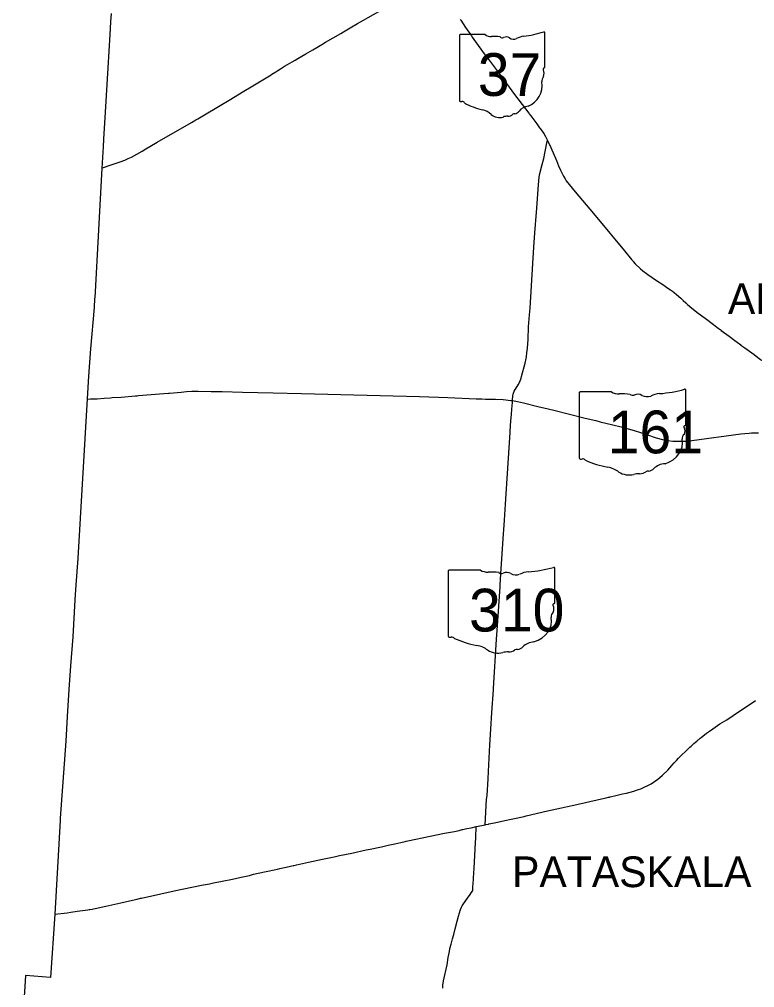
# Model space of a CAD drawing. Extents: x 1761803 to 2441803, y 509895 to 949895.
# Drawn here: x 1889790 to 1937717, y 814167 to 877258 of the extents above; entities that cross this region are included whole.
import ezdxf

# ---------------------------------------------------------------- set-up
doc = ezdxf.new("R2010")
doc.units = 0
for name, color, linetype in [('GM_X_County', 7, 'Continuous'), ('GM_X_County_Road', 7, 'Continuous'), ('GM_X_Minor_Lake', 7, 'Continuous'), ('GM_X_Minor_River_Text', 7, 'Continuous'), ('GM_X_Township_Road', 7, 'Continuous')]:
    doc.layers.add(name, color=color, linetype=linetype)

msp = doc.modelspace()

# ---------------------------------------------------------------- linework, layer by layer
at = {"layer": 'GM_X_County'}
msp.add_lwpolyline([(1895772, 877650), (1895741, 877103), (1895686, 876278), (1895557, 874101), (1895391, 871219), (1895282, 869451), (1895251, 868958), (1895161, 867565), (1894704, 859108), (1894692, 859059), (1894658, 858478), (1894436, 855788), (1894293, 854014), (1894201, 852542), (1893595, 842153), (1893596, 842130), (1893480, 840419), (1893416, 839442), (1893266, 837034), (1893131, 835129), (1893022, 833600), (1892908, 831832), (1892812, 830226), (1892456, 825219), (1892450, 825067), (1892092, 818948), (1891818, 814820), (1890201, 814965), (1890151, 814240), (1889790, 809054)], dxfattribs=at)
at = {"layer": 'GM_X_Minor_Lake'}
for points in [[(1918516, 877258), (1918561, 877195), (1918869, 876731)], [(1918869, 876731), (1919257, 876176), (1919311, 876097)], [(1919311, 876097), (1919969, 875165), (1920084, 875020), (1920403, 874603), (1921187, 873566), (1922063, 872370), (1922783, 871424), (1922990, 871153), (1923023, 871112), (1923129, 870979), (1923526, 870443), (1923699, 870198), (1923721, 870167)], [(1923721, 870167), (1923863, 869969), (1923971, 869820), (1924089, 869620), (1924222, 869362), (1924288, 869227), (1924426, 868903), (1924800, 868059), (1924937, 867708), (1925058, 867437), (1925191, 867168), (1925261, 867035), (1925356, 866866), (1925436, 866747), (1926026, 866022), (1926975, 864888), (1927441, 864346), (1929231, 862171), (1929693, 861615), (1929727, 861571), (1929778, 861514), (1929807, 861476), (1929927, 861334), (1930276, 860996), (1930438, 860864), (1930678, 860693), (1930758, 860637)], [(1923513, 864949), (1923599, 866204), (1923677, 867002), (1923708, 867217), (1923875, 867799), (1923970, 868202), (1924179, 869202), (1924222, 869362)], [(1922523, 853985), (1922749, 854861), (1922821, 855153), (1922845, 855272), (1922879, 855528), (1922907, 855832), (1922945, 856405), (1922980, 857216), (1923050, 858007), (1923079, 858446), (1923262, 861342), (1923322, 862423), (1923381, 863339), (1923492, 864694), (1923513, 864949)], [(1930758, 860637), (1931329, 860244), (1931735, 859974), (1932117, 859708), (1932239, 859631), (1932361, 859544), (1932476, 859453), (1932629, 859326), (1932897, 859089), (1933058, 858947), (1933240, 858782), (1933343, 858688), (1933621, 858447), (1933816, 858291), (1933954, 858190), (1934282, 857939), (1934484, 857781), (1935030, 857372), (1935247, 857210)], [(1935247, 857210), (1935489, 857030), (1935531, 857000)], [(1935531, 857000), (1935538, 856995), (1936062, 856612), (1936430, 856340), (1936584, 856226), (1936822, 856041)], [(1936822, 856041), (1936825, 856038), (1937073, 855856), (1937683, 855414)], [(1937683, 855414), (1937683, 855414), (1937817, 855317), (1938100, 855099), (1938165, 855046), (1938183, 855029)], [(1922119, 853166), (1922302, 853441), (1922318, 853463), (1922373, 853566), (1922410, 853645), (1922497, 853884), (1922523, 853985)], [(1899521, 852903), (1899572, 852908), (1900335, 852976), (1900693, 853000), (1901040, 853021), (1901445, 853028), (1902297, 853019), (1903020, 853003), (1904332, 852972), (1906325, 852923), (1908191, 852877), (1915868, 852675), (1917717, 852611), (1919561, 852540), (1919939, 852528), (1920182, 852521), (1920835, 852500), (1921323, 852479), (1921817, 852430)], [(1921926, 852285), (1921935, 852418), (1921966, 852756), (1921981, 852830), (1921996, 852893), (1922016, 852956), (1922040, 853022), (1922109, 853151), (1922119, 853166)], [(1894201, 852515), (1894422, 852524), (1894856, 852538), (1895318, 852568), (1895723, 852601), (1895738, 852602), (1895849, 852609), (1896428, 852649)], [(1896428, 852649), (1896436, 852649), (1897365, 852726), (1897479, 852735)], [(1897479, 852735), (1897561, 852741), (1899215, 852875), (1899521, 852903)], [(1921817, 852430), (1921935, 852418), (1922268, 852358), (1922653, 852267), (1923673, 852020), (1923987, 851940), (1924618, 851783), (1926681, 851278), (1927370, 851110), (1927651, 851042), (1928476, 850847), (1929012, 850708), (1929465, 850581), (1929859, 850461), (1930267, 850333), (1930679, 850201), (1931308, 850000), (1931717, 849889), (1932051, 849823), (1932389, 849774), (1932710, 849764), (1933054, 849764), (1933283, 849782), (1933617, 849823), (1936814, 850243), (1937070, 850274), (1937352, 850303), (1937523, 850314), (1937633, 850319), (1937968, 850327)], [(1921868, 851504), (1921897, 851865), (1921912, 852084), (1921926, 852285)], [(1921772, 850333), (1921777, 850424), (1921835, 851091)], [(1921835, 851091), (1921868, 851504)], [(1921407, 844632), (1921476, 845678), (1921772, 850333)], [(1921365, 844005), (1921407, 844632)], [(1921130, 840386), (1921179, 841138), (1921348, 843744), (1921365, 844005)], [(1921124, 840285), (1921124, 840285), (1921130, 840386)], [(1920341, 827782), (1920369, 828244), (1920460, 829990), (1920523, 830999), (1920588, 832094), (1920697, 833562), (1920700, 833669), (1920889, 836866), (1920933, 837436), (1921124, 840285)], [(1930963, 827452), (1931192, 827596), (1931406, 827748), (1931542, 827857), (1931722, 828014), (1932052, 828341), (1932326, 828647), (1932478, 828816), (1932617, 828971), (1932744, 829112), (1932919, 829302), (1933247, 829586), (1933338, 829677), (1933425, 829761), (1933501, 829834), (1933576, 829905), (1933635, 829957), (1933695, 830012), (1933762, 830074), (1933863, 830159), (1933952, 830235), (1934037, 830305), (1934071, 830333), (1934177, 830420), (1934236, 830465), (1934573, 830740), (1934769, 830884), (1935001, 831037), (1935452, 831347), (1935908, 831622), (1936321, 831894), (1937775, 832868)], [(1920143, 824777), (1920249, 826440), (1920275, 826693), (1920341, 827782)], [(1929363, 826849), (1929848, 826974), (1930026, 827037), (1930155, 827074), (1930300, 827127), (1930517, 827222), (1930746, 827339), (1930926, 827429), (1930963, 827452)], [(1925515, 825966), (1925928, 826058), (1927740, 826467), (1928042, 826536), (1928198, 826572)], [(1928198, 826572), (1928250, 826584), (1928300, 826596)], [(1928300, 826596), (1928672, 826682), (1929104, 826786), (1929340, 826842), (1929363, 826849)], [(1922832, 825358), (1924217, 825690), (1925118, 825877), (1925515, 825966)], [(1921953, 825165), (1922691, 825324), (1922832, 825358)], [(1918460, 824415), (1918647, 824461), (1918694, 824471), (1918950, 824526), (1919237, 824583), (1919575, 824657), (1919939, 824740), (1920143, 824777), (1920195, 824788)], [(1919494, 823109), (1919506, 823235), (1919520, 823603), (1919535, 823933), (1919575, 824657)], [(1920195, 824788), (1920378, 824829), (1920401, 824834)], [(1920401, 824834), (1920762, 824906), (1921437, 825054), (1921850, 825143)], [(1921850, 825143), (1921953, 825165)], [(1914994, 823702), (1915114, 823731), (1916575, 824027), (1917509, 824228), (1918147, 824339), (1918460, 824415)], [(1912667, 823197), (1913393, 823349), (1913830, 823447), (1914271, 823534), (1914654, 823621), (1914938, 823689)], [(1914938, 823689), (1914994, 823702)], [(1909558, 822545), (1910312, 822700), (1910647, 822768)], [(1910647, 822768), (1911471, 822936), (1912399, 823141), (1912667, 823197)], [(1919449, 822202), (1919450, 822218), (1919461, 822419), (1919481, 822714), (1919480, 822892), (1919490, 823072), (1919494, 823109)], [(1899880, 820467), (1901653, 820833), (1902189, 820937), (1902439, 820995), (1903012, 821114), (1903686, 821245), (1904240, 821364), (1904791, 821483), (1905061, 821551), (1905768, 821716), (1906617, 821891), (1906765, 821924), (1907373, 822059), (1907561, 822098), (1907630, 822117)], [(1907630, 822117), (1907699, 822135), (1907852, 822166), (1908627, 822339)], [(1908627, 822339), (1908628, 822340), (1909251, 822481), (1909558, 822545)], [(1919438, 822042), (1919442, 822093), (1919449, 822202)], [(1919397, 821402), (1919403, 821544), (1919417, 821705), (1919428, 821888), (1919438, 822042)], [(1919201, 820270), (1919302, 820426), (1919346, 820495), (1919353, 820709), (1919374, 820975)], [(1919374, 820975), (1919377, 821020), (1919382, 821138), (1919388, 821216), (1919397, 821402)], [(1897697, 819986), (1897746, 819996), (1899004, 820286), (1899880, 820467)], [(1919110, 820138), (1919200, 820268), (1919201, 820270)], [(1894526, 819286), (1894527, 819286), (1894619, 819305), (1894735, 819329), (1895418, 819471), (1896404, 819684), (1897171, 819858), (1897460, 819936), (1897697, 819986)], [(1917397, 814123), (1917398, 814247), (1917403, 814356), (1917419, 814462), (1917445, 814610), (1917671, 815660), (1917749, 816134), (1917820, 816520), (1917856, 816707), (1917929, 817006), (1918023, 817355), (1918103, 817636), (1918196, 818007), (1918329, 818497), (1918419, 818815), (1918540, 819251), (1918606, 819408), (1918662, 819504), (1918749, 819636), (1919011, 819990), (1919110, 820138)], [(1892092, 818948), (1892916, 819047), (1893156, 819084)], [(1893156, 819084), (1893560, 819145), (1893900, 819190), (1894253, 819238), (1894340, 819250), (1894375, 819255), (1894526, 819286)]]:
    msp.add_lwpolyline(points, dxfattribs=at)
at = {"layer": 'GM_X_Minor_River_Text'}
for points in [[(1911833, 876987), (1912220, 877211), (1912522, 877385), (1913218, 877770), (1913646, 878040), (1913666, 878050)], [(1910918, 876453), (1911359, 876713), (1911833, 876987)], [(1909505, 875618), (1909748, 875765), (1910734, 876345), (1910918, 876453)], [(1908454, 875001), (1908467, 875008), (1908776, 875185)], [(1908776, 875185), (1908914, 875263), (1908914, 875264)], [(1908914, 875264), (1909187, 875426), (1909187, 875427)], [(1909187, 875427), (1909505, 875618)], [(1907264, 874309), (1907579, 874492), (1907765, 874605)], [(1907765, 874605), (1907939, 874710), (1908454, 875001)], [(1906205, 873653), (1906250, 873680), (1906512, 873842)], [(1906512, 873842), (1906643, 873923), (1906808, 874026), (1907081, 874202), (1907264, 874309)], [(1895161, 867565), (1895215, 867584), (1895269, 867603), (1895716, 867755), (1896370, 867981), (1896665, 868083), (1896889, 868183), (1897092, 868286), (1897791, 868678), (1898027, 868822), (1898293, 868978), (1898781, 869255), (1901002, 870535), (1901290, 870706), (1901434, 870777), (1901851, 871038), (1902777, 871576), (1903580, 872067), (1904321, 872517), (1905012, 872933), (1906205, 873653)]]:
    msp.add_lwpolyline(points, dxfattribs=at)
at = {"layer": 'GM_X_Township_Road'}
for p, q in [((1924041, 874166), (1924041, 876376)), ((1918473, 876199), (1918473, 871972)), ((1920158, 876272), (1918528, 876272)), ((1924041, 874166), (1924041, 874166)), ((1928388, 852983), (1926349, 852983)), ((1933242, 850877), (1933242, 853088)), ((1926281, 852910), (1926281, 848684)), ((1933241, 850877), (1933242, 850877)), ((1917738, 841301), (1917738, 837074)), ((1919845, 841374), (1917807, 841374)), ((1924699, 839268), (1924699, 841478)), ((1924698, 839268), (1924699, 839268))]:
    msp.add_line(p, q, dxfattribs=at)
for centre, radius, start, end in [((1922058, 882034), 5905, 275.84447, 288.90645), ((1923980, 876386), 62, 351.86209, 97.738), ((1918537, 876208), 64.5, 98.1301, 188.1301), ((1920547, 876762), 626, 231.61951, 271.11188), ((1920754, 873899), 2246, 80.48669, 94.98827), ((1921264, 876230), 181, 219.79206, 297.10237), ((1921529, 875741), 375, 54.46668, 119.14113), ((1922014, 876411), 452, 233.85621, 294.82819), ((1922811, 874981), 1188, 97.34618, 120.76885), ((1924027, 874003), 95.9, 107.94398, 210.33697), ((1923417, 873724), 576, 340.03296, 23.64957), ((1923975, 874157), 66.3, 289.60381, 7.73413), ((1922389, 872959), 1477, 292.30889, 8.98584), ((1924264, 873240), 419, 136.8065, 186.92959), ((1918537, 871963), 65.1, 171.95839, 258.30661), ((1918547, 872396), 497, 267.33899, 280.60386), ((1918649, 871729), 179, 29.74838, 93.27175), ((1920910, 875526), 4265, 240.41292, 257.1985), ((1919638, 870074), 1334, 47.18416, 75.83597), ((1923011, 870786), 809, 94.40312, 142.57675), ((1921081, 871708), 847, 230.70037, 286.29184), ((1921571, 870246), 696, 85.69512, 111.20995), ((1921633, 871391), 451, 268.77702, 315.54927), ((1922041, 870982), 127, 65.75173, 132.64842), ((1921986, 871563), 477, 282.87319, 323.27711)]:
    msp.add_arc(centre, radius, start, end, dxfattribs=at)
for centre, major_axis, start_param, end_param in [((1926360, 852919), (80.6, 0), 1.712693, 3.28349), ((1928873, 853474), (782, 0), 4.042523, 4.731795), ((1930762, 858745), (7382, 0), 4.814394, 5.042369), ((1933164, 853097), (77.5, 0), 6.141152, 7.989035), ((1929133, 850610), (2808, 0), 1.404758, 1.657858), ((1929770, 852941), (226, 0), 3.836095, 5.185415), ((1930101, 852453), (469, 0), 0.950623, 2.079405), ((1930707, 853123), (564, 0), 4.081561, 5.145723), ((1931704, 851692), (1485, 0), 1.699011, 2.107814), ((1933224, 850714), (120, 0), 1.883978, 3.671073), ((1932461, 850435), (720, 0), 5.934695, 6.695948), ((1933159, 850868), (82.9, 0), 5.05454, 6.418171), ((1931176, 849670), (1846, 0), 5.101752, 6.440018), ((1933519, 849951), (524, 0), 2.387724, 3.262537), ((1926361, 848674), (81.4, 0), 3.00124, 4.508301), ((1926374, 849107), (621, 0), 4.665946, 4.897461), ((1926501, 848440), (224, 0), 0.519207, 1.627899), ((1929327, 852237), (5331, 0), 4.195997, 4.488961), ((1927738, 846785), (1668, 0), 0.823519, 1.323587), ((1930673, 848274), (597, 0), 4.937069, 5.64225), ((1931954, 847497), (1011, 0), 1.647645, 2.488434), ((1929542, 848419), (1058, 0), 4.026481, 4.996735), ((1930153, 846958), (870, 0), 1.495662, 1.94098), ((1930230, 848102), (564, 0), 4.691044, 5.507374), ((1930741, 847693), (159, 0), 1.147584, 2.315152), ((1917818, 841310), (80.6, 0), 1.712693, 3.28349), ((1920330, 841864), (782, 0), 4.042523, 4.731795), ((1920590, 839001), (2808, 0), 1.404758, 1.657858), ((1921227, 841332), (226, 0), 3.836095, 5.185415), ((1921559, 840843), (469, 0), 0.950623, 2.079405), ((1922164, 841513), (564, 0), 4.081561, 5.145723), ((1923161, 840083), (1485, 0), 1.699011, 2.107814), ((1922219, 847136), (7382, 0), 4.814394, 5.042369), ((1924622, 841488), (77.5, 0), 6.141152, 7.989035), ((1924681, 839105), (120, 0), 1.883978, 3.671073), ((1924616, 839259), (82.9, 0), 5.05454, 6.418171), ((1924976, 838342), (524, 0), 2.387724, 3.262537), ((1923918, 838826), (720, 0), 5.934695, 6.695948), ((1922633, 838061), (1846, 0), 5.101752, 6.440018), ((1917818, 837065), (81.4, 0), 3.00124, 4.508301), ((1917831, 837498), (621, 0), 4.665946, 4.897461), ((1917958, 836831), (224, 0), 0.519207, 1.627899), ((1920784, 840628), (5331, 0), 4.195997, 4.488961), ((1923411, 835888), (1011, 0), 1.647645, 2.488434), ((1919195, 835176), (1668, 0), 0.823519, 1.323587), ((1920999, 836810), (1058, 0), 4.026481, 4.996735), ((1921610, 835348), (870, 0), 1.495662, 1.94098), ((1921688, 836493), (564, 0), 4.691044, 5.507374), ((1922198, 836084), (159, 0), 1.147584, 2.315152), ((1922130, 836665), (597, 0), 4.937069, 5.64225)]:
    msp.add_ellipse(centre, major_axis=major_axis, ratio=0.8, start_param=start_param, end_param=end_param, dxfattribs=at)

# ---------------------------------------------------------------- texts
at = {"layer": 'GM_X_County_Road'}
for s, p in [('ALEXANDRIA', (1935975, 858058)), ('PATASKALA', (1921904, 820715))]:
    msp.add_text(s, height=2000, rotation=0.00001, dxfattribs=at).set_placement(p)
at = {"layer": 'GM_X_Township_Road'}
for s, p in [('37', (1919674, 872270)), ('161', (1928142, 848982)), ('310', (1919104, 837373))]:
    msp.add_text(s, height=2784.4, dxfattribs=at).set_placement(p)

doc.saveas('drawing.dxf')
